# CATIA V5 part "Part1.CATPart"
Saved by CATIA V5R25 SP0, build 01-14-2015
Part number: Part1
Bounding box of the stored display mesh (mm): x -12.5 to 12.5, y 0 to 150, z 0 to 30
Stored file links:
  D:\kin uygulama8\Part1.CATPart
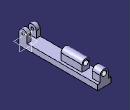
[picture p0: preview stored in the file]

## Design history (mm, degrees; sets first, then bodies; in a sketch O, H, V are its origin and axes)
Body1 (main body)
  Sketch1 on xy-plane, origin (0, 0, 0), H (1, 0, 0), V (0, 1, 0)
    line L1 (-12.5, 150) -> (12.5, 150)
    line L2 (12.5, 150) -> (12.5, 0)
    line L3 (12.5, 0) -> (-12.5, 0)
    line L4 (-12.5, 0) -> (-12.5, 150)
    length L2 = 150
    length L1 = 25
    horizontal: L1 H, L3 H
    vertical: L2 V, L4 V
    symmetry: L4 L2 V
    coincidence: L3 H
  Pad1: profile Sketch1, direction (0, 0, 1), length 10
  Sketch2 on end face of Pad1, origin (0, 0, 10), H (1, 0, 0), V (0, 1, 0)
    point P1 (-12.5, 15)
    line L1 (-12.5, 15) -> (-5, 15)
    line L2 (-5, 15) -> (-5, 0)
    line L3 (-5, 0) -> (-12.5, 0)
    line L4 (-12.5, 0) -> (-12.5, 15)
    point P2 (-5, 15)
    point P3 (-5, 0)
    point P4 (-12.5, 0)
    reference projected line E1 (-12.5, 150) -> (-12.5, 0) from edge [face of Pad1 from Sketch1.L4 | end face of Pad1]
    point P5 (12.5, 15)
    point P6 (5, 15)
    point P7 (5, 0)
    point P8 (12.5, 0)
    line L5 (12.5, 15) -> (5, 15)
    line L6 (5, 15) -> (5, 0)
    line L7 (5, 0) -> (12.5, 0)
    line L8 (12.5, 0) -> (12.5, 15)
    length L4 = 15
    length L3 = 7.5
    horizontal: L1 H, L3 H
    vertical: L2 V, L4 V
    coincidence: L3 H, L4 E1
    symmetry: P1 P5 V, P2 P6 V, P3 P7 V, P4 P8 V, L1 L5 V, L2 L6 V, L3 L7 V, L4 L8 V
  Pad2: profile Sketch2, direction (0, 0, 1), length 20
  TritangentFillet1: Face1 face of Pad2, Face2 face of Pad2 from Sketch2.L5, RemoveFace end face of Pad2
  TritangentFillet2: Face1 face of Pad2 from Sketch2.L1, Face2 face of Pad2, RemoveFace end face of Pad2
  Sketch3 on face of Pad2, origin (12.5, 9.8323, 23.6454), H (0, 1, 0), V (0, 0, 1)
    point P1 (-2.3323, -1.1454)
    reference projected arc E1 centre (-2.3323, -1.1454) radius 7.5 from (5.1677, -1.1454) to (-9.8323, -1.1454) ccw from edge [face of Pad2 | face of TritangentFillet1]
    concentricity: E1 P1
  Hole1: placed by Sketch3, at (12.5, 7.5, 22.5) direction (-1, 0, 0), diameter 5, through (limit type 3)
  Sketch4 on end face of Pad1, origin (0, 0, 10), H (1, 0, 0), V (0, 1, 0)
    line L1 (-7.5, 150) -> (7.5, 150)
    line L2 (7.5, 150) -> (7.5, 75)
    line L3 (7.5, 75) -> (-7.5, 75)
    line L4 (-7.5, 75) -> (-7.5, 150)
    reference projected line E1 (12.5, 150) -> (-12.5, 150) from edge [face of Pad1 from Sketch1.L1 | end face of Pad1]
    length L2 = 75
    length L1 = 15
    horizontal: L1 H, L3 H
    vertical: L2 V, L4 V
    symmetry: L2 L4 V
    coincidence: L1 E1
  Pad3: profile Sketch4, direction (0, 0, 1), length 20
  TritangentFillet3: Face1 face of Pad3 from Sketch4.L2, Face2 face of Pad3 from Sketch4.L4, RemoveFace end face of Pad3
  Sketch5 on yz-plane, origin (0, 0, 0), H (0, 1, 0), V (0, 0, 1)
    line L1 (115, 34.309) -> (135, 34.309)
    line L2 (135, 34.309) -> (135, 10)
    line L3 (135, 10) -> (115, 10)
    line L4 (115, 10) -> (115, 34.309)
    reference projected line E1 (150, 10) -> (150, 30) from edge [face of Pad3 | face of Pad3 from Sketch4.L2]
    reference projected line E2 (0, 10) -> (150, 10) from edge [face of Pad2 | end face of Pad1]
    length L1 = 20
    distance L2 E1 = 15
    horizontal: L1 H, L3 H
    vertical: L2 V, L4 V
    coincidence: L3 E2
  Pocket1: profile Sketch5, direction (-1, 0, 0), length 20, mirrored extent
  Sketch6 on face of Pad3, origin (-2.6087, 150, 25.3701), H (1, 0, 0), V (0, 0, -1)
    point P1 (2.6087, 2.8701)
    reference projected arc E1 centre (2.6087, 2.8701) radius 7.5 from (-4.8913, 2.8701) to (10.1087, 2.8701) ccw from edge [face of Pad3 | face of TritangentFillet3]
    concentricity: E1 P1
  Hole2: placed by Sketch6, at (0, 150, 22.5) direction (0, -1, 0), diameter 10, through (limit type 3)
